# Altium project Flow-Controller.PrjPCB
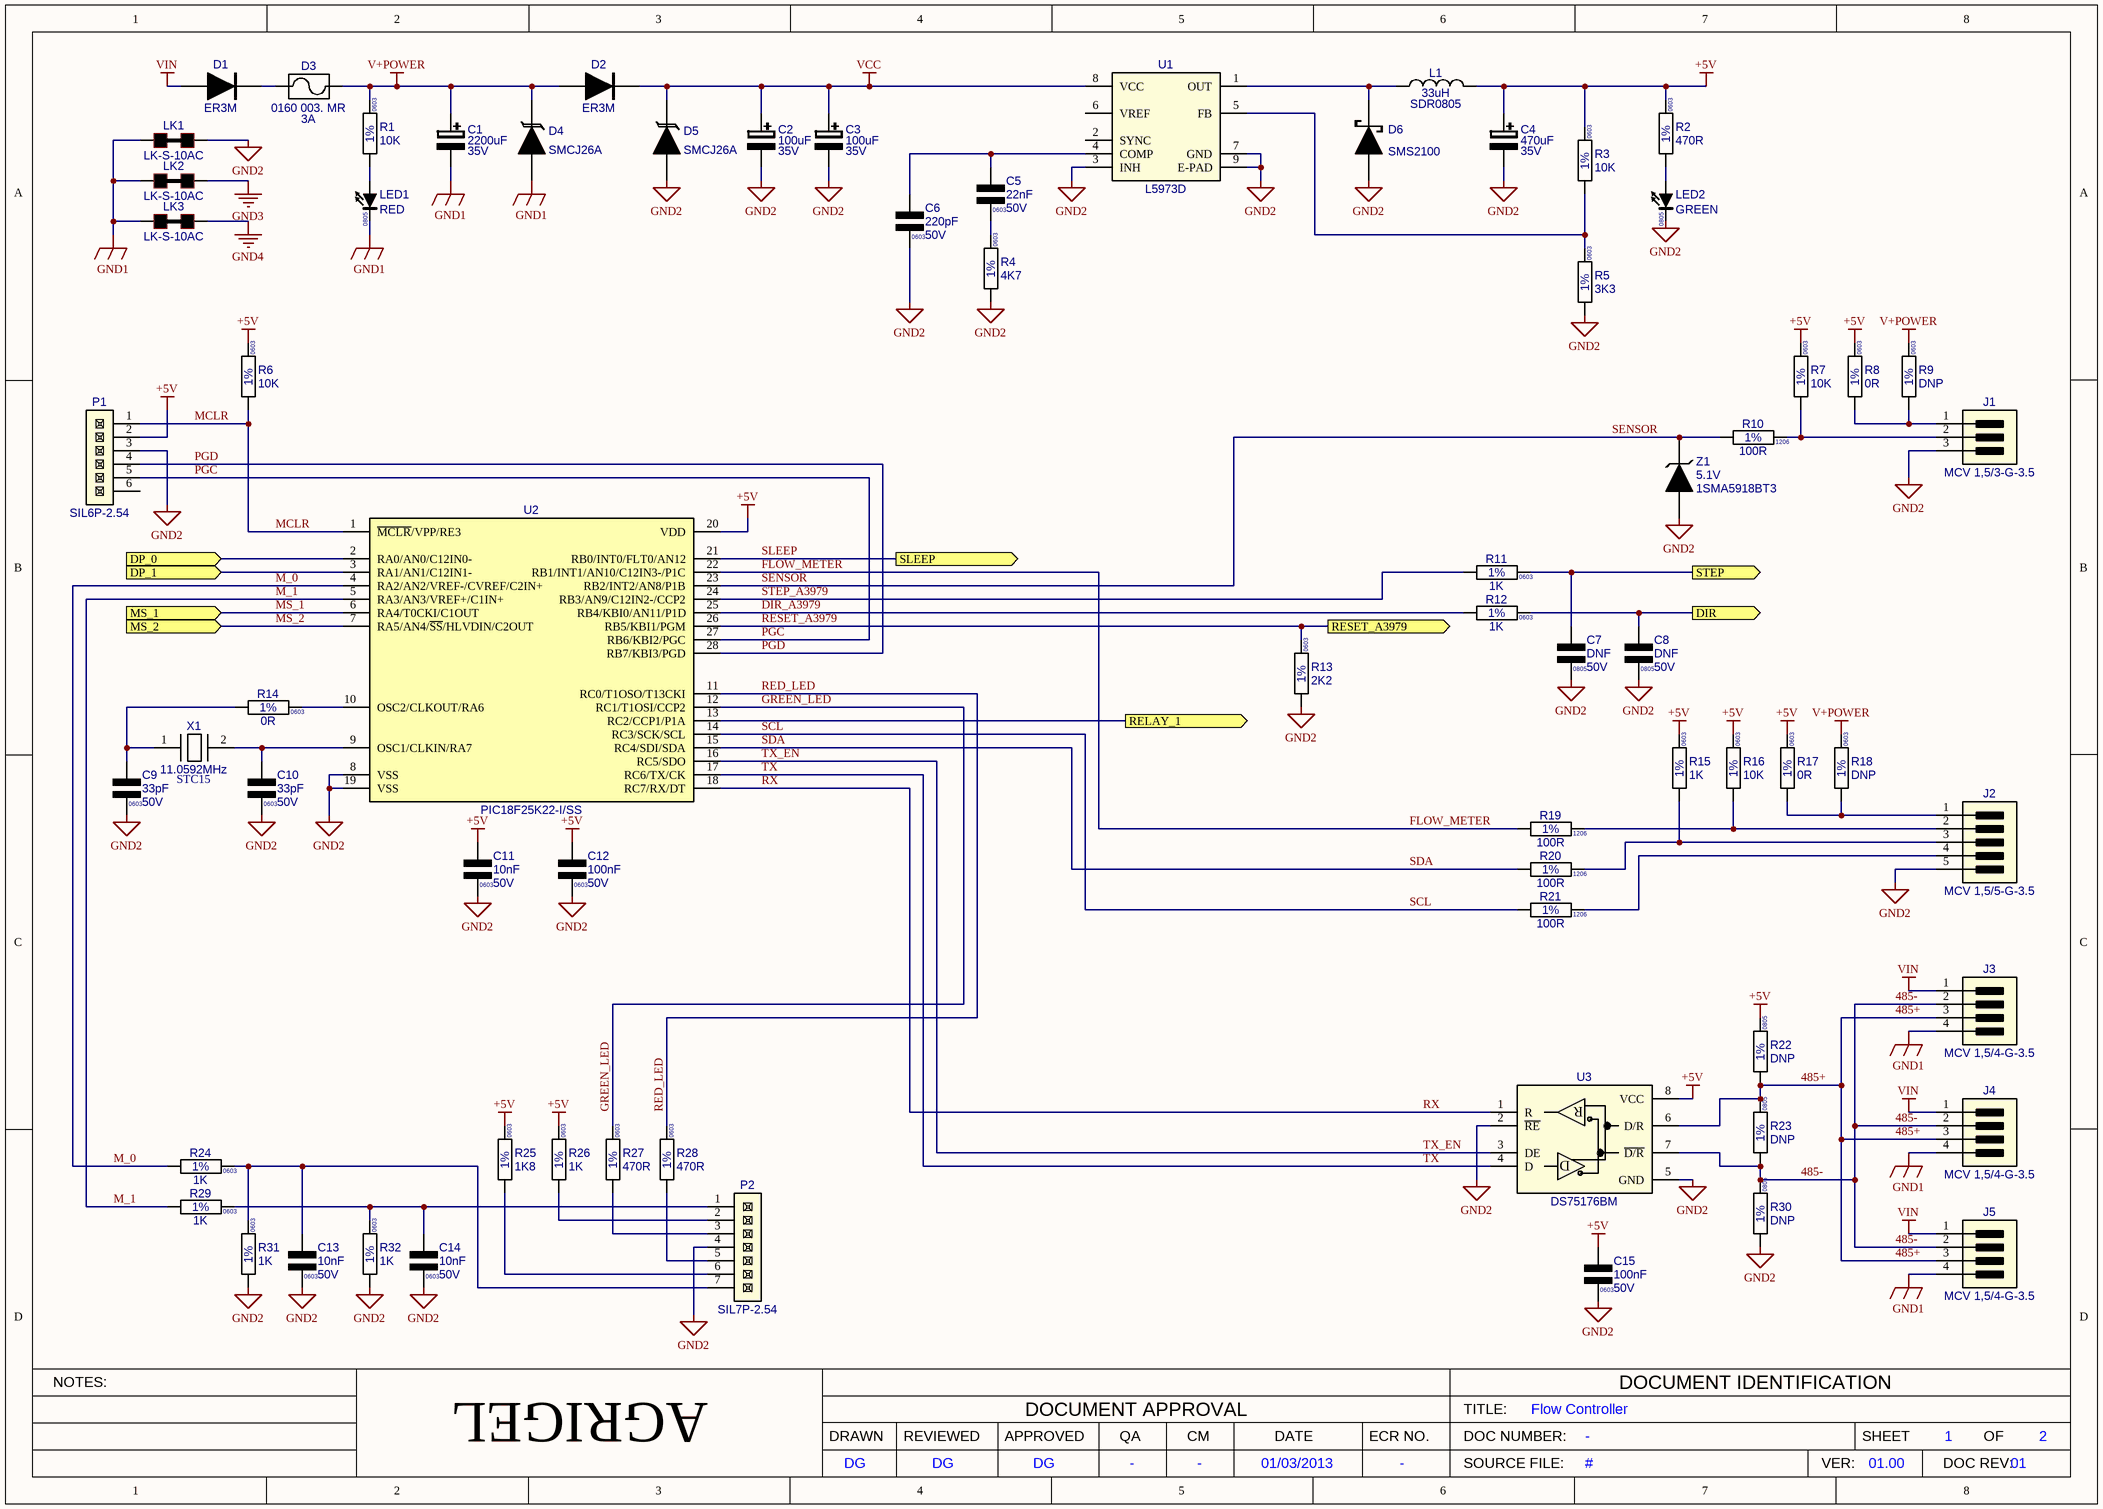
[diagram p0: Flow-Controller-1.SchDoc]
Version: 01.00; SCH_Title: Flow Controller; SCH_SheetTotal: 2; SCH_Reviewed: DG; SCH_QA: -; SCH_Number: -; SCH_FILENAME: Flow-Controller.SCH; SCH_ECR: -; SCH_DRAWN: DG; SCH_DocRev: 01; SCH_Date: 01/03/2013; SCH_CM: -; SCH_Approved: DG; PCB_TITLE: FLOW CONTROLLER PCB; PCB_Plot File [Assy]: Flow-Controller [Assy]; PCB_Plot File: Flow-Controller [Panel]; PCB_ECRNo: -; PCB_Drawn: EDM; PCB_Drawing Number: -; PCB_DocRevision: 01; PCB_Company Name: AGRIGEL
2 sheets, 113 parts. Net scope: flat (ports and power ports of the same name join across sheets).
Board files: Flow-Controller.PcbDoc, Flow-Controller [Assy].PcbDoc, Flow-Controller [Panel].PcbDoc
Sheets:
  Flow-Controller-1.SchDoc
  Flow-Controller-2.SchDoc

## Sheet Flow-Controller-1.SchDoc: #
size A3; ApprovedBy: #; DrawnBy: #; DocumentNumber: #; Revision: #; SheetNumber: 1; SheetTotal: 2; DocumentRevision: #; Reviewed: #; QA: #; CM: #; ECR: #; PageSetup: Record=PageOptions|CenterHorizontal=True|CenterVertical=True|PrintScale=0.97|XCorrection=1.00|YCorrection=1.00|PrintKind=1|BorderSize=5000000|LeftOffset=0|BottomOffset=0|Orientation=2|PaperLength=1000|PaperWidth=1000|Scale=100|PaperSource=7|PrintQuality=-4|MediaType=1|DitherType=10|PaperKind=A3|PrintScaleMode=1

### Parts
C1  value 2200uF  Voltage: 35V  [EL-RAD-16X31.5]  (hidden comment: CAP-EL_2200uF_35V_20%-YXF)
C2  value 100uF  Voltage: 35V  [CAP-EL-SMD-10x10.5]  (hidden comment: 100uF35V-20%-EEVFC)
C3  value 100uF  Voltage: 35V  [CAP-EL-SMD-10x10.5]  (hidden comment: 100uF35V-20%-EEVFC)
C4  value 470uF  Voltage: 35V  [CAP-EL-SMD-10x10.5]  (hidden comment: 470uF-35V-20%-LZ)
C5  value 22nF  Voltage: 50V  Text1: 0603  [CAPC0603X85N]  (hidden comment: 22nF_C0603_50V_10%_X7R)
C6  value 220pF  Voltage: 50V  Text1: 0603  [CAPC0603X85N]  (hidden comment: 220pF_C0603_50V_10%_NP0)
C7  value DNF  Voltage: 50V  Text1: 0805  [CAPC0805X110N]  (hidden comment: DNF_C0805_50V_10%_X7R)
C8  value DNF  Voltage: 50V  Text1: 0805  [CAPC0805X110N]  (hidden comment: DNF_C0805_50V_10%_X7R)
C9  value 33pF  Voltage: 50V  Text1: 0603  [CAPC0603X85N]  (hidden comment: 33pF_C0603_50V_10%_NP0)
C10  value 33pF  Voltage: 50V  Text1: 0603  [CAPC0603X85N]  (hidden comment: 33pF_C0603_50V_10%_NP0)
C11  value 10nF  Voltage: 50V  Text1: 0603  [CAPC0603X85N]  (hidden comment: 10nF_C0603_50V_10%_X7R)
C12  value 100nF  Voltage: 50V  Text1: 0603  [CAPC0603X85N]  (hidden comment: 100nF_C0603_50V_10%_X7R)
C13  value 10nF  Voltage: 50V  Text1: 0603  [CAPC0603X85N]  (hidden comment: 10nF_C0603_50V_10%_X7R)
C14  value 10nF  Voltage: 50V  Text1: 0603  [CAPC0603X85N]  (hidden comment: 10nF_C0603_50V_10%_X7R)
C15  value 100nF  Voltage: 50V  Text1: 0603  [CAPC0603X85N]  (hidden comment: 100nF_C0603_50V_10%_X7R)
D1  ER3M  [SMC]
D2  ER3M  [SMC]
D3  value 3A  [LF-0160]  (hidden comment: 0160 003. MR)
D4  SMCJ26A  [SMC]
D5  SMCJ26A  [SMC]
D6  SMS2100  [DO-213AB]
J1  MCV 1,5/3-G-3.5  [MCV350-3-V]
J2  MCV 1,5/5-G-3.5  [MCV350-5-V]
J3  MCV 1,5/4-G-3.5  [MCV350-4-V]
J4  MCV 1,5/4-G-3.5  [MCV350-4-V]
J5  MCV 1,5/4-G-3.5  [MCV350-4-V]
L1  value 33uH  [SDR0805]  (hidden comment: SDR0805-330K)
LED1  value RED  Text2: 0805  [LED0805-Red]  (hidden comment: RED_0805_SMD)
LED2  value GREEN  Text2: 0805  [LED0805-Green]  (hidden comment: GREEN_0805_SMD)
LK1  Part Number: LK-S-10AC  [SLINK-10A-C]  (hidden comment: Link-SMD-10A-Closed)  (no BOM)
LK2  Part Number: LK-S-10AC  [SLINK-10A-C]  (hidden comment: Link-SMD-10A-Closed)  (no BOM)
LK3  Part Number: LK-S-10AC  [SLINK-10A-C]  (hidden comment: Link-SMD-10A-Closed)  (no BOM)
P1  SIL6P-2.54  [SIL6P-2.54]
P2  SIL7P-2.54  [SIL7P-2.54]
R1  value 10K  Tol: 1%  Text1: 0603  [RESC0603X60N]  (hidden comment: 10K_R0603_1%)
R2  value 470R  Tol: 1%  Text1: 0603  [RESC0603X60N]  (hidden comment: 470R_R0603_1%)
R3  value 10K  Tol: 1%  Text1: 0603  [RESC0603X60N]  (hidden comment: 10K_R0603_1%)
R4  value 4K7  Tol: 1%  Text1: 0603  [RESC0603X60N]  (hidden comment: 4K7_R0603_1%)
R5  value 3K3  Tol: 1%  Text1: 0603  [RESC0603X60N]  (hidden comment: 3K3_R0603_1%)
R6  value 10K  Tol: 1%  Text1: 0603  [RESC0603X60N]  (hidden comment: 10K_R0603_1%)
R7  value 10K  Tol: 1%  Text1: 0603  [RESC0603X60N]  (hidden comment: 10K_R0603_1%)
R8  value 0R  Tol: 1%  Text1: 0603  [RESC0603X60N]  (hidden comment: 0R_R0603_1%)
R9  value DNP  Tol: 1%  Text1: 0603  [RESC0603X60N]  (hidden comment: DNP_R0603_1%)
R10  value 100R  Tol: 1%  Text1: 1206  [RESC1206X71N]  (hidden comment: 100R_R1206_1%)
R11  value 1K  Tol: 1%  Text1: 0603  [RESC0603X60N]  (hidden comment: 1K_R0603_1%)
R12  value 1K  Tol: 1%  Text1: 0603  [RESC0603X60N]  (hidden comment: 1K_R0603_1%)
R13  value 2K2  Tol: 1%  Text1: 0603  [RESC0603X60N]  (hidden comment: 2K2_R0603_1%)
R14  value 0R  Tol: 1%  Text1: 0603  [RESC0603X60N]  (hidden comment: 0R_R0603_1%)
R15  value 1K  Tol: 1%  Text1: 0603  [RESC0603X60N]  (hidden comment: 1K_R0603_1%)
R16  value 10K  Tol: 1%  Text1: 0603  [RESC0603X60N]  (hidden comment: 10K_R0603_1%)
R17  value 0R  Tol: 1%  Text1: 0603  [RESC0603X60N]  (hidden comment: 0R_R0603_1%)
R18  value DNP  Tol: 1%  Text1: 0603  [RESC0603X60N]  (hidden comment: DNP_R0603_1%)
R19  value 100R  Tol: 1%  Text1: 1206  [RESC1206X71N]  (hidden comment: 100R_R1206_1%)
R20  value 100R  Tol: 1%  Text1: 1206  [RESC1206X71N]  (hidden comment: 100R_R1206_1%)
R21  value 100R  Tol: 1%  Text1: 1206  [RESC1206X71N]  (hidden comment: 100R_R1206_1%)
R22  value DNP  Tol: 1%  Text1: 0805  [RESC0805X65N]  (hidden comment: DNP_R0805_1%)
R23  value DNP  Tol: 1%  Text1: 0805  [RESC0805X65N]  (hidden comment: DNP_R0805_1%)
R24  value 1K  Tol: 1%  Text1: 0603  [RESC0603X60N]  (hidden comment: 1K_R0603_1%)
R25  value 1K8  Tol: 1%  Text1: 0603  [RESC0603X60N]  (hidden comment: 1K8_R0603_1%)
R26  value 1K  Tol: 1%  Text1: 0603  [RESC0603X60N]  (hidden comment: 1K_R0603_1%)
R27  value 470R  Tol: 1%  Text1: 0603  [RESC0603X60N]  (hidden comment: 470R_R0603_1%)
R28  value 470R  Tol: 1%  Text1: 0603  [RESC0603X60N]  (hidden comment: 470R_R0603_1%)
R29  value 1K  Tol: 1%  Text1: 0603  [RESC0603X60N]  (hidden comment: 1K_R0603_1%)
R30  value DNP  Tol: 1%  Text1: 0805  [RESC0805X65N]  (hidden comment: DNP_R0805_1%)
R31  value 1K  Tol: 1%  Text1: 0603  [RESC0603X60N]  (hidden comment: 1K_R0603_1%)
R32  value 1K  Tol: 1%  Text1: 0603  [RESC0603X60N]  (hidden comment: 1K_R0603_1%)
U1  Part Number: L5973D  [HSOP8]  (hidden comment: L5973D-HSOP8)
U2  PIC18F25K22-I/SS  [SSOP28]
U3  DS75176BM  [SO8]
X1  Text2: STC15  Text1: 11.0592MHz  [XT-HEX15]  (hidden comment: XTAL_11.0592MHz_STCX15)
Z1  value 5.1V  [SMA]  (hidden comment: 1SMA5918BT3)

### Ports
DIR, DP_0, DP_1, MS_1, MS_2, RELAY_1, RESET_A3979, SLEEP, STEP

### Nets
+5V: C4.1 C11.1 C12.1 C15.1 L1.2 P1.2 R2.1 R3.1 R6.1 R7.1 R8.1 R15.1 R16.1 R17.1 R22.1 R25.1 R26.1 U2.20(VDD) U3.8(VCC)
GND1: C1.2 D4.2(A) J3.4 J4.4 J5.4 LED1.1(K) LK1.1 LK2.1 LK3.1
GND2: C2.2 C3.2 C4.2 C6.2 C7.2 C8.2 C9.2 C10.2 C11.2 C12.2 C13.2 C14.2 C15.2 D5.2(A) D6.2(A) J1.3 J2.5 LED2.1(K) LK1.2 P1.3 P2.4 R4.2 R5.2 R13.2 R30.2 R31.2 R32.2 U1.3(INH) U1.7(GND) U1.9(E-PAD) U2.8(VSS) U2.19(VSS) U3.2(~{RE}) U3.5(GND) Z1.2(A)
GND3: LK2.2
GND4: LK3.2
V+POWER: C1.1 D2.2(A) D3.2 D4.1(C) R1.1 R9.1 R18.1
VCC: C2.1 C3.1 D2.1(C) D5.1(C) U1.8(VCC)
VIN: D1.2(A) J3.1 J4.1 J5.1
485+: J3.3 J4.3 J5.3 R22.2 R23.1 U3.6(D/R)
485-: J3.2 J4.2 J5.2 R23.2 R30.1 U3.7(~{D/R})
DIR_A3979: R12.1 U2.25(RB4/KBI0/AN11/P1D)
FLOW_METER: R19.1 U2.22(RB1/INT1/AN10/C12IN3-/P1C)
GREEN_LED: R27.1 U2.12(RC1/T1OSI/CCP2)
M_0: R24.1 U2.4(RA2/AN2/VREF-/CVREF/C2IN+)
M_1: R29.1 U2.5(RA3/AN3/VREF+/C1IN+)
MCLR: P1.1 R6.2 U2.1(~{MCLR}/VPP/RE3)
MS_1: U2.6(RA4/T0CKI/C1OUT) ; port MS_1
MS_2: U2.7(RA5/AN4/~{SS}/HLVDIN/C2OUT) ; port MS_2
PGC: P1.5 U2.27(RB6/KBI2/PGC)
PGD: P1.4 U2.28(RB7/KBI3/PGD)
RED_LED: R28.1 U2.11(RC0/T1OSO/T13CKI)
RESET_A3979: R13.1 U2.26(RB5/KBI1/PGM) ; port RESET_A3979
RX: U2.18(RC7/RX/DT) U3.1(R)
SCL: R21.1 U2.14(RC3/SCK/SCL)
SDA: R20.1 U2.15(RC4/SDI/SDA)
SENSOR: R10.1 U2.23(RB2/INT2/AN8/P1B) Z1.1(C)
SLEEP: U2.21(RB0/INT0/FLT0/AN12) ; port SLEEP
STEP_A3979: R11.1 U2.24(RB3/AN9/C12IN2-/CCP2)
TX: U2.17(RC6/TX/CK) U3.4(D)
TX_EN: U2.16(RC5/SDO) U3.3(DE)
NetC5_1: C5.1 C6.1 U1.4(COMP)
NetC5_2: C5.2 R4.1
NetC7_1: C7.1 R11.2 ; port STEP
NetC8_1: C8.1 R12.2 ; port DIR
NetC9_1: C9.1 R14.1 X1.1
NetC10_1: C10.1 U2.9(OSC1/CLKIN/RA7) X1.2
NetC13_1: C13.1 P2.7 R24.2 R31.1
NetC14_1: C14.1 P2.1 R29.2 R32.1
NetD1_1: D1.1(C) D3.1
NetD6_1: D6.1(C) L1.1 U1.1(OUT)
NetJ1_1: J1.1 R8.2 R9.2
NetJ1_2: J1.2 R7.2 R10.2
NetJ2_1: J2.1 R17.2 R18.2
NetJ2_2: J2.2 R16.2 R19.2
NetJ2_3: J2.3 R15.2 R20.2
NetJ2_4: J2.4 R21.2
NetLED1_2: LED1.2(A) R1.2
NetLED2_2: LED2.2(A) R2.2
NetP2_2: P2.2 R26.2
NetP2_3: P2.3 R27.2
NetP2_5: P2.5 R28.2
NetP2_6: P2.6 R25.2
NetR3_2: R3.2 R5.1 U1.5(FB)
NetR14_2: R14.2 U2.10(OSC2/CLKOUT/RA6)
NetR46_1: U2.13(RC2/CCP1/P1A) ; port RELAY_1
NetR47_1: U2.2(RA0/AN0/C12IN0-) ; port DP_0
NetR53_1: U2.3(RA1/AN1/C12IN1-) ; port DP_1

Not connected (* = marked no-connect by the designer): P1 6; U1 2(SYNC) 6(VREF)

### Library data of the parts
C1 = 2200uF_35V_20%_V-YXF: Cap Electrolytic THP Radial - Low Imp; Manufacturer: Rubycon; Part Number: 35YXF2200M; Tol: 20%
C2 C3 = 100uF-35V-20%-EEVFC_V: Cap Electrolytic SMD Low Imp; Manufacturer: Panasonic; Part Number: EEVFC1V101P; Tol: 20%
C4 = 470uF-35V-20%-LZ_V: Cap Electrolytic SMD Low Imp; Manufacturer: KJ Electronics; Part Number: 35LZ471MLC10×10.5EC; Tol: 20%
C5 = 22nF_0603N_50V_10%_X7R_V: Cap Ceramic X7R; Manufacturer: Various; Part Number: 22nF 0603 50V 10% X7R; Board Tech: SMD; Tol: 10%
C6 = 220pF_0603N_50V_10%_NP0_V: Cap Ceramic NP0; Manufacturer: Various; Part Number: 220pF 0603 50V 10% NP0; Board Tech: SMD; Tol: 10%
C7 C8 = DNF_0805N_50V_10%_X7R_V: Do not Fit - Cap Ceramic X7R; Manufacturer: Various; Board Tech: SMD; Tol: 10%
C9 C10 = 33pF_0603N_50V_10%_NP0_V: Cap Ceramic NP0; Manufacturer: Various; Part Number: 33pF 0603 50V 10% NP0; Board Tech: SMD; Tol: 10%
C11 C13 C14 = 10nF_0603N_50V_10%_X7R_V: Cap Ceramic X7R; Manufacturer: Various; Part Number: 10nF 0603 50V 10% X7R; Board Tech: SMD; Tol: 10%; Reutech PN: 5910-CA-0402
C12 C15 = 100nF_0603N_50V_10%_X7R_V: Cap Ceramic X7R; Manufacturer: Various; Part Number: 100nF 0603 50V 10% X7R; Board Tech: SMD; Tol: 10%
D1 D2 = ER3M_SMC_H: Diode Rectifier (1000V 3A); Manufacturer: Diotec; Board Tech: SMD
D3 = FUSE_0160_003.MR_3AMP: Fuseblock with Slow-Blo Fuse; Manufacturer: LITTLEFUSE; Board Tech: SMD
D4 D5 = SMCJ26A_V: TVS 1500W SMC; Manufacturer: Various; Board Tech: SMD
D6 = SMS2100_V: Diode Schottky Rectifier 2Amp 100V; Manufacturer: Diotec; Board Tech: SMD; EDM-PN: DIO15
J1 = MCV 1,5/3-G-3.5: Header Pluggable 3.5mm Vertical; Manufacturer: Phoenix; Board Tech: THP
J2 = MCV 1,5/5-G-3.5: Header Pluggable 3.5mm Vertical; Manufacturer: Phoenix; Board Tech: THP
J3-J5 = MCV 1,5/4-G-3.5: Header Pluggable 3.5mm Vertical; Manufacturer: Phoenix; Board Tech: THP
L1 = 33uH_SDR0805_H: Inductor Power; Manufacturer: Bourns; Board Tech: SMD; Tol: 10%
LED1 = RED_0805_SMD_V: LED SMD 0805 Red; Manufacturer: Various; EDM-PN: LED7
LED2 = GREEN_0805_SMD_V: LED SMD 0805 Green; Manufacturer: Various; EDM-PN: LED17
LK1-LK3 = Link-SMD-10A-Closed: Link SMD Closed 10Amp; Manufacturer: Generic
P1 = SIL6P-2.54: Header SIL Male THP, 2.54mm Pitch; Manufacturer: Various
P2 = SIL7P-2.54: Header SIL Male THP, 2.54mm Pitch; Manufacturer: Various
R1 R3 R6 R7 R16 = 10K_0603_V: Resistor Chip SMD; Manufacturer: Various; Part Number: 10K 0603 1%; Watt: 100mW; EDM-PN: RES120
R2 R27 R28 = 470R_0603_V: Resistor Chip SMD; Manufacturer: Various; Part Number: 470R 0603 1%; Watt: 100mW; EDM-PN: RES127
R4 = 4K7_0603_V: Resistor Chip SMD; Manufacturer: Various; Part Number: 4K7 0603 1%; Watt: 100mW
R5 = 3K3_0603_V: Resistor Chip SMD; Manufacturer: Various; Part Number: 3K3 0603 1%; Watt: 100mW
R8 R17 = 0R_0603_V: Resistor Chip SMD; Manufacturer: Various; Part Number: 0R 0603 1%; Watt: 100mW; EDM-PN: RES117
R9 R18 = DNP_0603_V: Resistor Chip SMD; Manufacturer: Various; Watt: 100mW
R10 R19-R21 = 100R_1206_H: Resistor Chip SMD; Manufacturer: Various; Part Number: 100R 1206 1%; Watt: 250mW
R11 R12 R24 R29 = 1K_0603_H: Resistor Chip SMD; Manufacturer: Various; Part Number: 1K 0603 1%; Watt: 100mW
R13 = 2K2_0603_V: Resistor Chip SMD; Manufacturer: Various; Part Number: 2K2 0603 1%; Watt: 100mW; EDM-PN: RES232
R14 = 0R_0603_H: Resistor Chip SMD; Manufacturer: Various; Part Number: 0R 0603 1%; Watt: 100mW; EDM-PN: RES117
R15 R26 R31 R32 = 1K_0603_V: Resistor Chip SMD; Manufacturer: Various; Part Number: 1K 0603 1%; Watt: 100mW
R22 R23 R30 = DNP_0805_V: Resistor Chip SMD; Manufacturer: Various; Watt: 125mW
R25 = 1K8_0603_V: Resistor Chip SMD; Manufacturer: Various; Part Number: 1K8 0603 1%; Watt: 100mW
U1 = L5973D-HSOP8: IC Switching Regulator 2.5A; Manufacturer: ST; Board Tech: SMT
U2 = PIC18F25K22-I/SS_SSOP28: IC Microcontroller 8-Bit; Manufacturer: Microchip; Board Tech: SMD
U3 = DS75176BM_SO8: IC 3.3V RS-485 Drivers and Receivers; Manufacturer: National; Board Tech: SMD
X1 = XTAL_11.0592MHz_STCX15: Crystal - HEX15; Manufacturer: STC; Part Number: STCX15-11.0592MHz; Board Tech: SMD; Value: XTAL_STCX15-11.0592MHz
Z1 = 1SMA5918BT3_X: Zener Diode 1.5W; Manufacturer: On Semi; Board Tech: SMT

## Sheet Flow-Controller-2.SchDoc: #
size A3; ApprovedBy: #; DrawnBy: #; DocumentNumber: #; Revision: #; SheetNumber: 2; SheetTotal: 2; DocumentRevision: #; Reviewed: #; QA: #; CM: #; ECR: #; PageSetup: Record=PageOptions|CenterHorizontal=True|CenterVertical=True|PrintScale=0.97|XCorrection=1.00|YCorrection=1.00|PrintKind=1|BorderSize=5000000|LeftOffset=0|BottomOffset=0|Orientation=2|PaperLength=1000|PaperWidth=1000|Scale=100|PaperSource=7|PrintQuality=-4|MediaType=1|DitherType=10|PaperKind=A3|PrintScaleMode=1
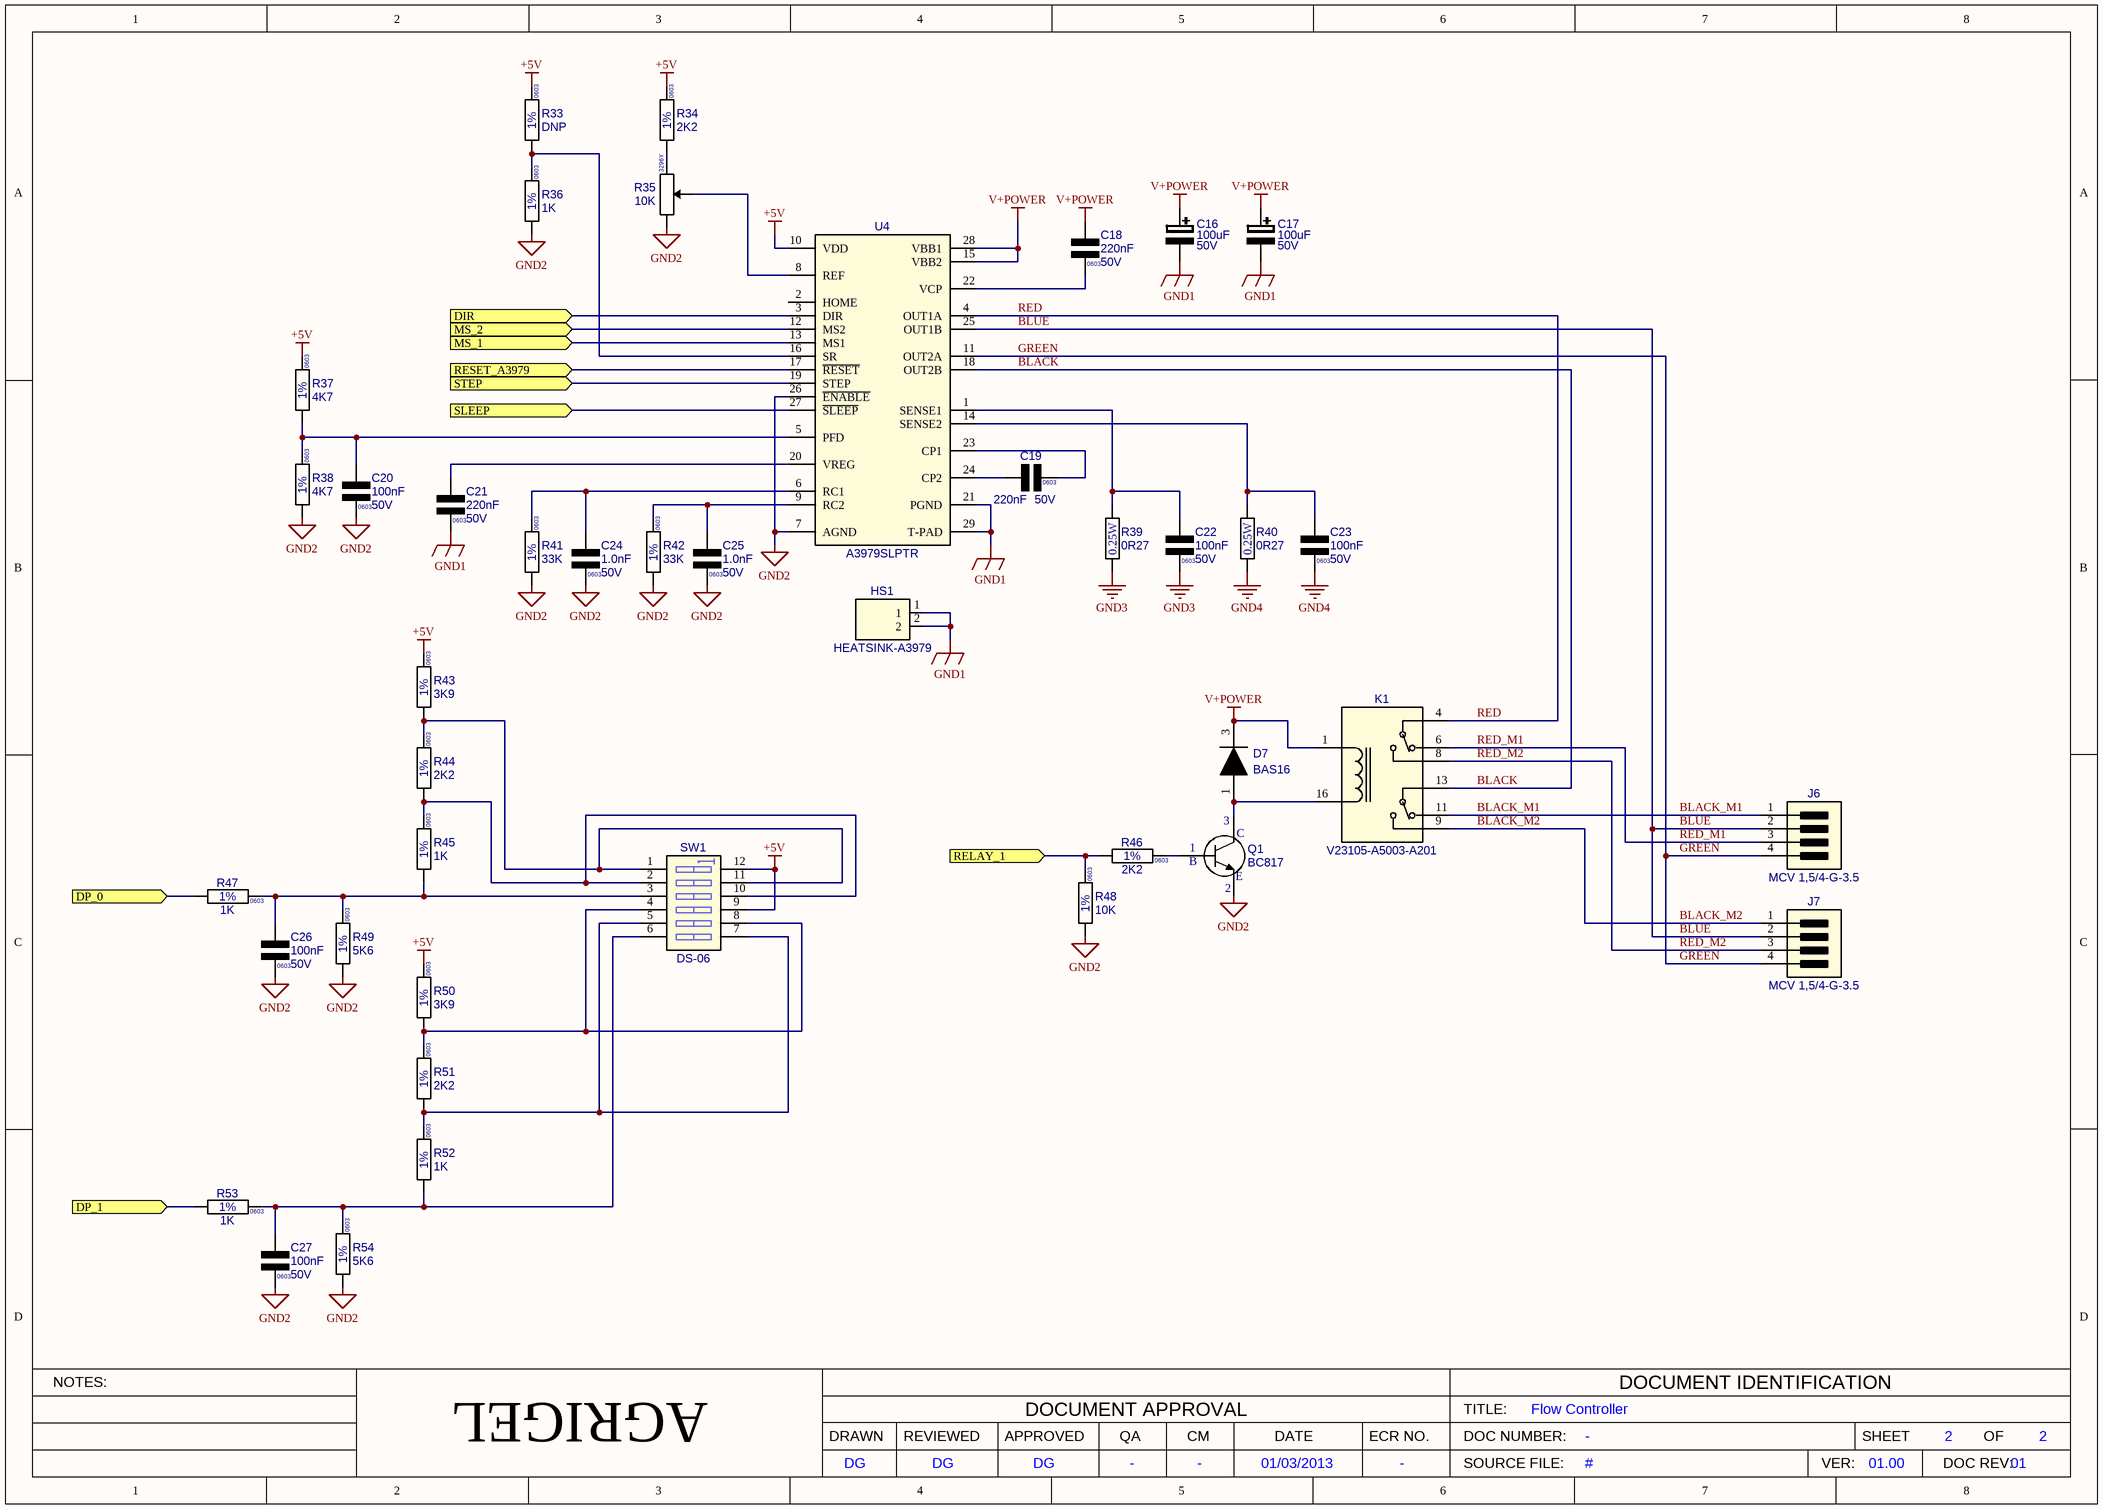
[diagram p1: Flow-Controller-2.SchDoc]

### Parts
C16  value 100uF  Voltage: 50V  [CAP-EL-SMD-8x10.5]  (hidden comment: 100uF-50V-20%-LZ)
C17  value 100uF  Voltage: 50V  [CAP-EL-SMD-8x10.5]  (hidden comment: 100uF-50V-20%-LZ)
C18  value 220nF  Voltage: 50V  Text1: 0603  [CAPC0603X85N]  (hidden comment: 220nF_C0603_50V_10%_X7R)
C19  value 220nF  Voltage: 50V  Text1: 0603  [CAPC0603X85N]  (hidden comment: 220nF_C0603_50V_10%_X7R)
C20  value 100nF  Voltage: 50V  Text1: 0603  [CAPC0603X85N]  (hidden comment: 100nF_C0603_50V_10%_X7R)
C21  value 220nF  Voltage: 50V  Text1: 0603  [CAPC0603X85N]  (hidden comment: 220nF_C0603_50V_10%_X7R)
C22  value 100nF  Voltage: 50V  Text1: 0603  [CAPC0603X85N]  (hidden comment: 100nF_C0603_50V_10%_X7R)
C23  value 100nF  Voltage: 50V  Text1: 0603  [CAPC0603X85N]  (hidden comment: 100nF_C0603_50V_10%_X7R)
C24  value 1.0nF  Voltage: 50V  Text1: 0603  [CAPC0603X85N]  (hidden comment: 1.0nF_C0603_50V_10%_X7R)
C25  value 1.0nF  Voltage: 50V  Text1: 0603  [CAPC0603X85N]  (hidden comment: 1.0nF_C0603_50V_10%_X7R)
C26  value 100nF  Voltage: 50V  Text1: 0603  [CAPC0603X85N]  (hidden comment: 100nF_C0603_50V_10%_X7R)
C27  value 100nF  Voltage: 50V  Text1: 0603  [CAPC0603X85N]  (hidden comment: 100nF_C0603_50V_10%_X7R)
D7  BAS16  [SOT23]
HS1  Heatsink-A3979  [HEATSINK-A3979]
J6  MCV 1,5/4-G-3.5  [MCV350-4-V]
J7  MCV 1,5/4-G-3.5  [MCV350-4-V]
K1  Part Number: V23105-A5003-A201  [REL-D2n]  (hidden comment: V23105-A5003-A201-12V)
Q1  BC817  [SOT23]
R33  value DNP  Tol: 1%  Text1: 0603  [RESC0603X60N]  (hidden comment: DNP_R0603_1%)
R34  value 2K2  Tol: 1%  Text1: 0603  [RESC0603X60N]  (hidden comment: 2K2_R0603_1%)
R35  value 10K  Text1: 3296Y  [3296Y-THP]  (hidden comment: 3296Y-1-103)
R36  value 1K  Tol: 1%  Text1: 0603  [RESC0603X60N]  (hidden comment: 1K_R0603_1%)
R37  value 4K7  Tol: 1%  Text1: 0603  [RESC0603X60N]  (hidden comment: 4K7_R0603_1%)
R38  value 4K7  Tol: 1%  Text1: 0603  [RESC0603X60N]  (hidden comment: 4K7_R0603_1%)
R39  value 0R27  Watt: 0.25W  [RES-0.250W]  (hidden comment: 0R27-0.250W-5%)
R40  value 0R27  Watt: 0.25W  [RES-0.250W]  (hidden comment: 0R27-0.250W-5%)
R41  value 33K  Tol: 1%  Text1: 0603  [RESC0603X60N]  (hidden comment: 33K_R0603_1%)
R42  value 33K  Tol: 1%  Text1: 0603  [RESC0603X60N]  (hidden comment: 33K_R0603_1%)
R43  value 3K9  Tol: 1%  Text1: 0603  [RESC0603X60N]  (hidden comment: 3K9_R0603_1%)
R44  value 2K2  Tol: 1%  Text1: 0603  [RESC0603X60N]  (hidden comment: 2K2_R0603_1%)
R45  value 1K  Tol: 1%  Text1: 0603  [RESC0603X60N]  (hidden comment: 1K_R0603_1%)
R46  value 2K2  Tol: 1%  Text1: 0603  [RESC0603X60N]  (hidden comment: 2K2_R0603_1%)
R47  value 1K  Tol: 1%  Text1: 0603  [RESC0603X60N]  (hidden comment: 1K_R0603_1%)
R48  value 10K  Tol: 1%  Text1: 0603  [RESC0603X60N]  (hidden comment: 10K_R0603_1%)
R49  value 5K6  Tol: 1%  Text1: 0603  [RESC0603X60N]  (hidden comment: 5K6_R0603_1%)
R50  value 3K9  Tol: 1%  Text1: 0603  [RESC0603X60N]  (hidden comment: 3K9_R0603_1%)
R51  value 2K2  Tol: 1%  Text1: 0603  [RESC0603X60N]  (hidden comment: 2K2_R0603_1%)
R52  value 1K  Tol: 1%  Text1: 0603  [RESC0603X60N]  (hidden comment: 1K_R0603_1%)
R53  value 1K  Tol: 1%  Text1: 0603  [RESC0603X60N]  (hidden comment: 1K_R0603_1%)
R54  value 5K6  Tol: 1%  Text1: 0603  [RESC0603X60N]  (hidden comment: 5K6_R0603_1%)
SW1  DS-06  [DIP-SW6]
U4  A3979SLPTR  [TSSOP28-4.4-LP]

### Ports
DIR, DP_0, DP_1, MS_1, MS_2, RELAY_1, RESET_A3979, SLEEP, STEP

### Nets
+5V: R33.1 R34.1 R37.1 R43.1 R50.1 SW1.9(B4) SW1.12(B1) U4.10(VDD)
GND1: C16.2 C17.2 C21.2 HS1.1 HS1.2 U4.21(PGND) U4.29(T-PAD)
GND2: C20.2 C24.2 C25.2 C26.2 C27.2 Q1.2(E) R35.3 R36.2 R38.2 R41.2 R42.2 R48.2 R49.2 R54.2 U4.7(AGND) U4.26(~{ENABLE})
GND3: C22.2 R39.1
GND4: C23.2 R40.1
V+POWER: C16.1 C17.1 C18.1 D7.3(C) K1.1 U4.15(VBB2) U4.28(VBB1)
BLACK: K1.13 U4.18(OUT2B)
BLACK_M1: J6.1 K1.11
BLACK_M2: J7.1 K1.9
BLUE: J6.2 J7.2 U4.25(OUT1B)
GREEN: J6.4 J7.4 U4.11(OUT2A)
MS_1: U4.13(MS1) ; port MS_1
MS_2: U4.12(MS2) ; port MS_2
RED: K1.4 U4.4(OUT1A)
RED_M1: J6.3 K1.6
RED_M2: J7.3 K1.8
RESET_A3979: U4.17(~{RESET}) ; port RESET_A3979
SLEEP: U4.27(~{SLEEP}) ; port SLEEP
NetC7_1: U4.19(STEP) ; port STEP
NetC8_1: U4.3(DIR) ; port DIR
NetC18_2: C18.2 U4.22(VCP)
NetC19_1: C19.1 U4.24(CP2)
NetC19_2: C19.2 U4.23(CP1)
NetC20_1: C20.1 R37.2 R38.1 U4.5(PFD)
NetC21_1: C21.1 U4.20(VREG)
NetC22_1: C22.1 R39.2 U4.1(SENSE1)
NetC23_1: C23.1 R40.2 U4.14(SENSE2)
NetC24_1: C24.1 R41.1 U4.6(RC1)
NetC25_1: C25.1 R42.1 U4.9(RC2)
NetC26_1: C26.1 R45.2 R47.2 R49.1 SW1.3(A3)
NetC27_1: C27.1 R52.2 R53.2 R54.1 SW1.6(A6)
NetD7_1: D7.1(A) K1.16 Q1.3(C)
NetQ1_1: Q1.1(B) R46.2
NetR33_2: R33.2 R36.1 U4.16(SR)
NetR34_2: R34.2 R35.1
NetR35_2: R35.2 U4.8(REF)
NetR43_2: R43.2 R44.1 SW1.1(A1) SW1.11(B2)
NetR44_2: R44.2 R45.1 SW1.2(A2) SW1.10(B3)
NetR46_1: R46.1 R48.1 ; port RELAY_1
NetR47_1: R47.1 ; port DP_0
NetR50_2: R50.2 R51.1 SW1.4(A4) SW1.8(B5)
NetR51_2: R51.2 R52.1 SW1.5(A5) SW1.7(B6)
NetR53_1: R53.1 ; port DP_1

Not connected (* = marked no-connect by the designer): U4 2(HOME)

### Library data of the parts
C16 C17 = 100uF-50V-20%-LZ_V: Cap Electrolytic SMD Low Imp; Manufacturer: KJ Electronics; Part Number: 50LZ101MLC8×10.5EC; Tol: 20%
C18 C21 = 220nF_0603N_50V_10%_X7R_V: Cap Ceramic X7R; Manufacturer: Various; Part Number: 220nF 0603 50V 10% X7R; Board Tech: SMD; Tol: 10%
C19 = 220nF_0603N_50V_10%_X7R_H: Cap Ceramic X7R; Manufacturer: Various; Part Number: 220nF 0603 50V 10% X7R; Board Tech: SMD; Tol: 10%
C20 C22 C23 C26 C27 = 100nF_0603N_50V_10%_X7R_V: as C12 on sheet Flow-Controller-1
C24 C25 = 1nF_0603N_50V_10%_X7R_V: Cap Ceramic X7R; Manufacturer: Various; Part Number: 1.0nF 0603 50V 10% X7R; Board Tech: SMD; Tol: 10%; Reutech PN: 5910-CA-0401
D7 = BAS16_SOT23-3N_V: Diode Small Signal; Manufacturer: Fairchild; Board Tech: SMD
HS1 = Heatsink-A3979: Heatsink Vertical PCB Mount A3979; Manufacturer: Agrigel; Board Tech: THP
J6 J7 = MCV 1,5/4-G-3.5: as J3 on sheet Flow-Controller-1
K1 = V23105-A5003-A201-12V: Relay DPDT 12V 3A; Manufacturer: Tyco/Axicom; Board Tech: THP
Q1 = BC817_SOT23: Transistor NPN General Purpose; Manufacturer: Various; Board Tech: SMD; EDM-PN: TRN12
R33 = DNP_0603_V: as R9 on sheet Flow-Controller-1
R34 R44 R51 = 2K2_0603_V: as R13 on sheet Flow-Controller-1
R35 = 10K_3296Y-1-103_THP_V: Variable Resistor THP; Manufacturer: BOURNS
R36 R45 R52 = 1K_0603_V: as R15 on sheet Flow-Controller-1
R37 R38 = 4K7_0603_V: as R4 on sheet Flow-Controller-1
R39 R40 = 0R27-0.250W-5%_V: Resistor Metal Film; Manufacturer: Various; Part Number: 0R27 5% 0.25W; Board Tech: THP; Tol: 5%
R41 R42 = 33K_0603_V: Resistor Chip SMD; Manufacturer: Various; Part Number: 33K 0603 1%; Watt: 100mW
R43 R50 = 3K9_0603_V: Resistor Chip SMD; Manufacturer: Various; Part Number: 3K9 0603 1%; Watt: 100mW
R46 = 2K2_0603_H: Resistor Chip SMD; Manufacturer: Various; Part Number: 2K2 0603 1%; Watt: 100mW; EDM-PN: RES232
R47 R53 = 1K_0603_H: as R11 on sheet Flow-Controller-1
R48 = 10K_0603_V: as R1 on sheet Flow-Controller-1
R49 R54 = 5K6_0603_V: Resistor Chip SMD; Manufacturer: Various; Part Number: 5K6 0603 1%; Watt: 100mW
SW1 = SW-DIP-DS-06: DIP Slide Switch; Manufacturer: Diptronics; Board Tech: THP
U4 = A3979SLPTR_TSSOP28: IC Microstepping DMOS Driver; Manufacturer: Allegro; Board Tech: SMD

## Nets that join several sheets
+5V: Flow-Controller-1 (19 pins), Flow-Controller-2 (8 pins)
GND1: Flow-Controller-1 (9 pins), Flow-Controller-2 (7 pins)
GND2: Flow-Controller-1 (35 pins), Flow-Controller-2 (16 pins)
GND3: Flow-Controller-1 (LK2.2), Flow-Controller-2 (C22.2 R39.1)
GND4: Flow-Controller-1 (LK3.2), Flow-Controller-2 (C23.2 R40.1)
V+POWER: Flow-Controller-1 (7 pins), Flow-Controller-2 (7 pins)
MS_1: Flow-Controller-1 (U2.6), Flow-Controller-2 (U4.13)
MS_2: Flow-Controller-1 (U2.7), Flow-Controller-2 (U4.12)
NetC7_1: Flow-Controller-1 (C7.1 R11.2), Flow-Controller-2 (U4.19)
NetC8_1: Flow-Controller-1 (C8.1 R12.2), Flow-Controller-2 (U4.3)
NetR46_1: Flow-Controller-1 (U2.13), Flow-Controller-2 (R46.1 R48.1)
NetR47_1: Flow-Controller-1 (U2.2), Flow-Controller-2 (R47.1)
NetR53_1: Flow-Controller-1 (U2.3), Flow-Controller-2 (R53.1)
RESET_A3979: Flow-Controller-1 (R13.1 U2.26), Flow-Controller-2 (U4.17)
SLEEP: Flow-Controller-1 (U2.21), Flow-Controller-2 (U4.27)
